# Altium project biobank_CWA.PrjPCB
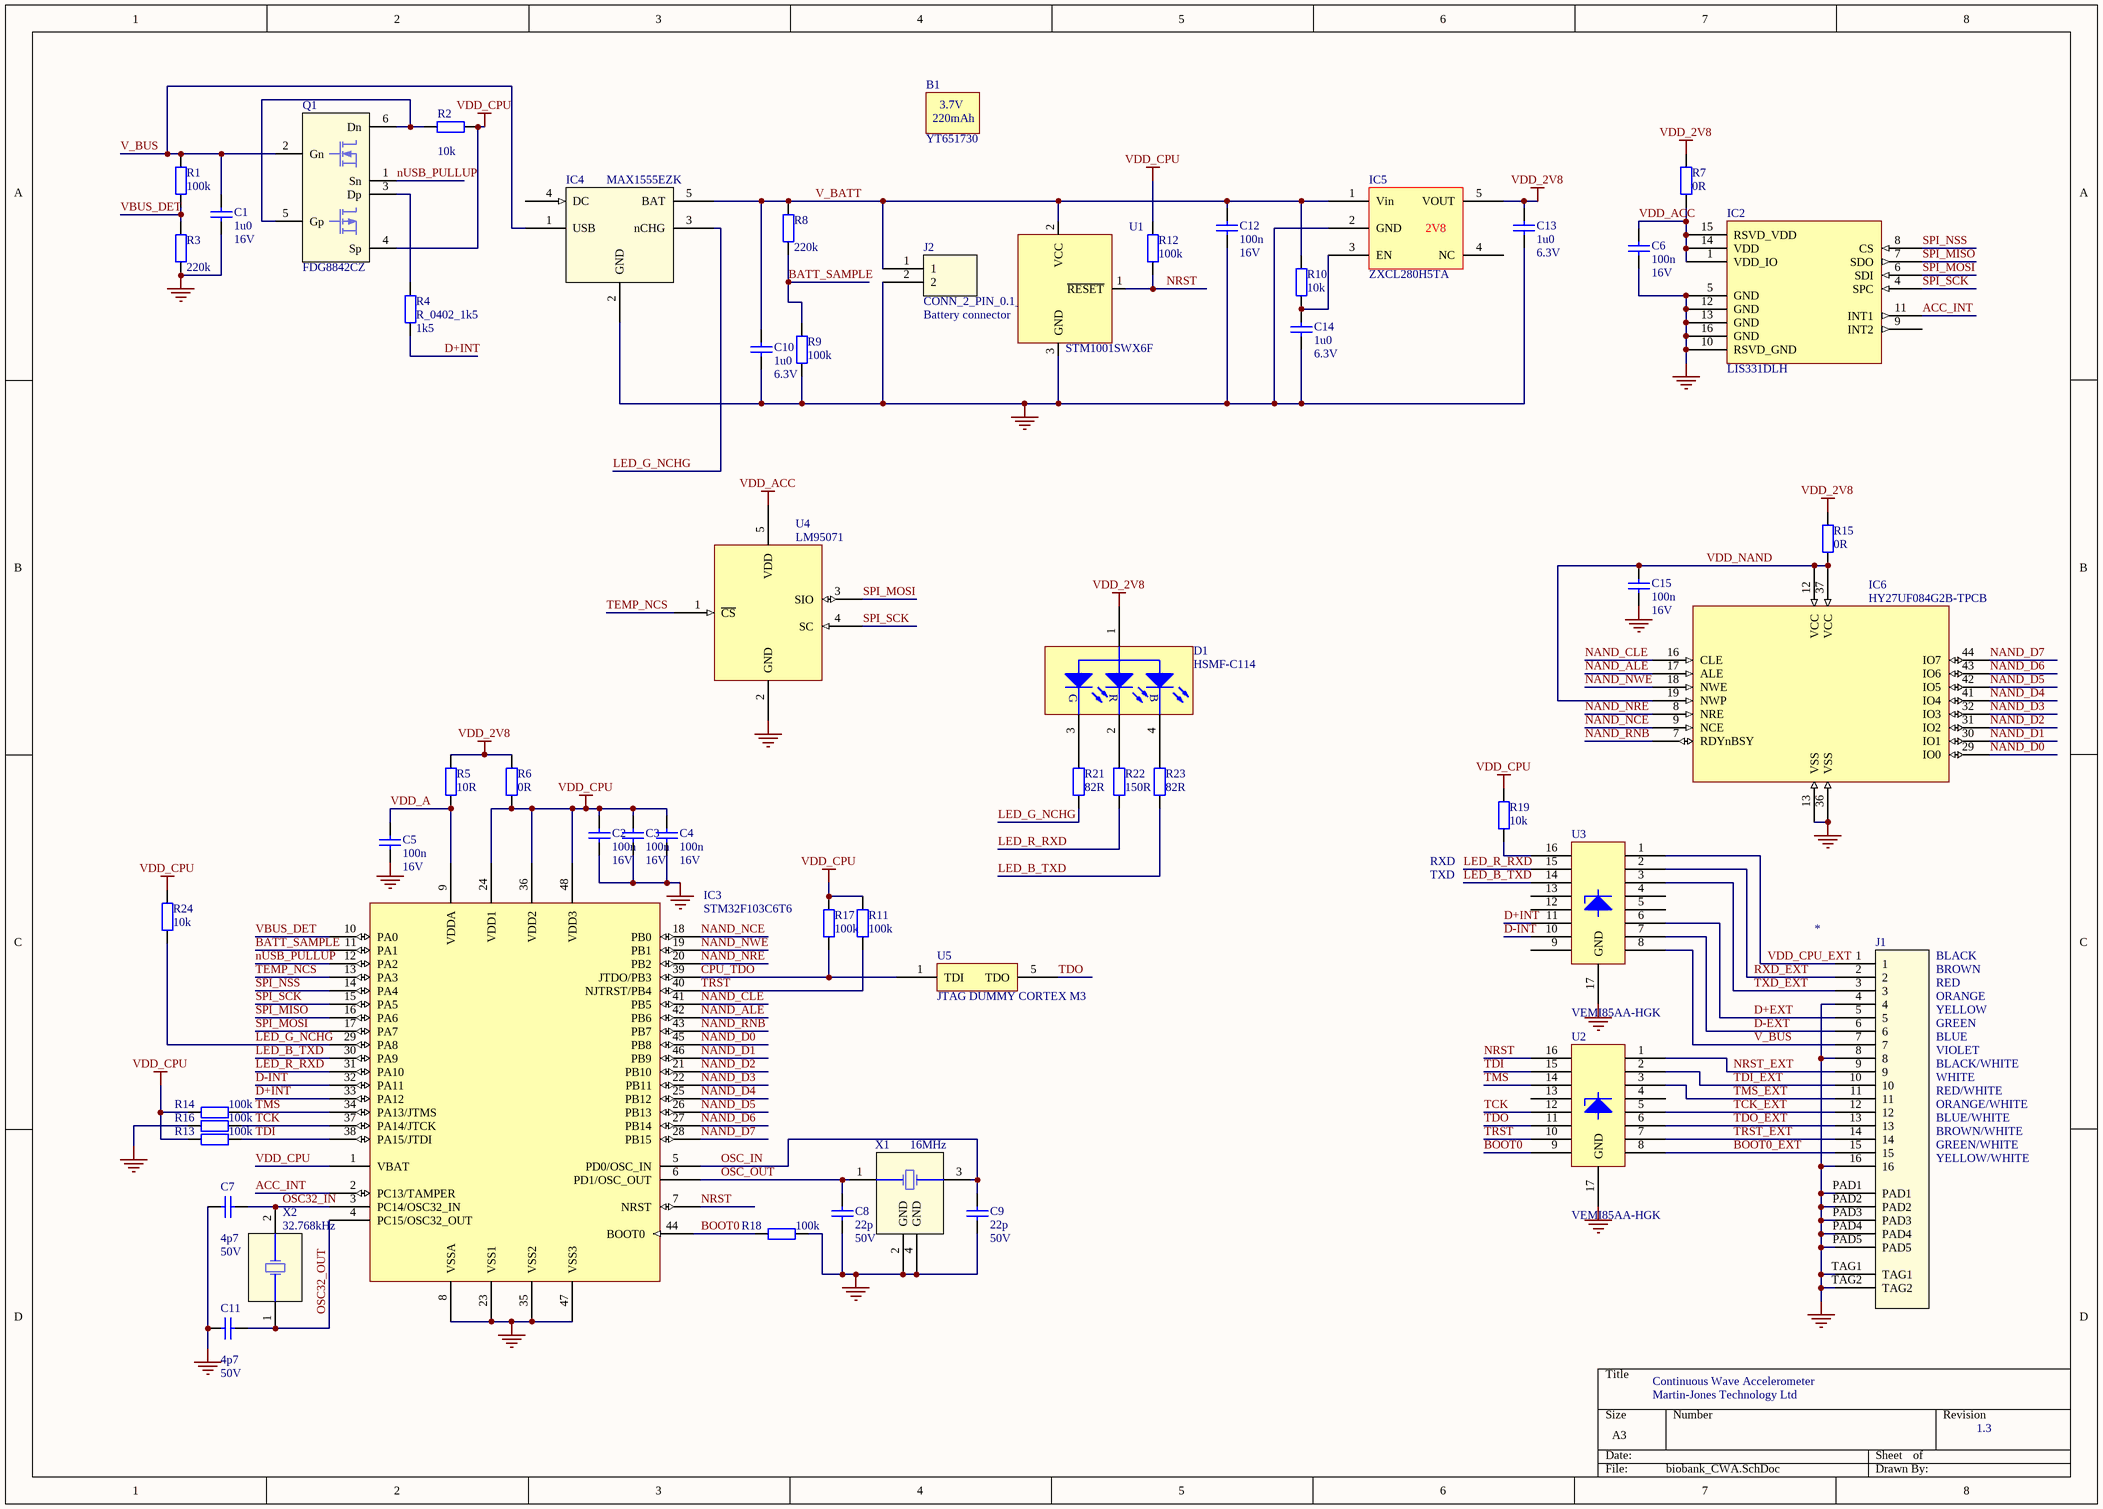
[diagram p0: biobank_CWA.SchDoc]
1 sheet, 55 parts. Net scope: global (net labels, ports and power ports of the same name join across sheets).
Board file: biobank_CWA.PcbDoc

## Sheet biobank_CWA.SchDoc
size A3; PageSetup: Record=PageOptions|CenterHorizontal=True|CenterVertical=True|PrintScale=0.73|XCorrection=1.00|YCorrection=1.00|PrintKind=0|BorderSize=5000000|LeftOffset=0|BottomOffset=0|Orientation=2|PaperLength=1000|PaperWidth=1000|Scale=100|PaperSource=15|PrintQuality=300|MediaType=1|DitherType=10|PaperKind=A4|PrintScaleMode=1

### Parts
B1  YT651730
C1  value 1u0  V: 16V  [0603-NP]  (hidden comment: C_0603_1u0_16V_X7R)
C2  value 100n  V: 16V  [0402-NP]
C3  value 100n  V: 16V  [0402-NP]
C4  value 100n  V: 16V  [0402-NP]
C5  value 100n  V: 16V  [0402-NP]
C6  value 100n  V: 16V  [0402-NP]
C7  value 4p7  V: 50V  [0402-NP]  (hidden comment: C_0402_4p7)
C8  value 22p  V: 50V  [0402-NP]  (hidden comment: C_0402_22p_NPO)
C9  value 22p  V: 50V  [0402-NP]  (hidden comment: C_0402_22p_NPO)
C10  value 1u0  V: 6.3V  [0402-NP]  (hidden comment: C_0402_1u0_6V3_X5R)
C11  value 4p7  V: 50V  [0402-NP]  (hidden comment: C_0402_4p7)
C12  value 100n  V: 16V  [0402-NP]
C13  value 1u0  V: 6.3V  [0402-NP]  (hidden comment: C_0402_1u0_6V3_X5R)
C14  value 1u0  V: 6.3V  [0402-NP]  (hidden comment: C_0402_1u0_6V3_X5R)
C15  value 100n  V: 16V  [0402-NP]
D1  HSMF-C114  [AVAGO_HSMF_C114]
IC2  LIS331DLH  [LGA16]
IC3  STM32F103C6T6  [F-QFP7x7-G48/N]
IC4  MAX1555EZK  [SOT23-5]
IC5  ZXCL280H5TA  [SC70]
IC6  HY27UF084G2B-TPCB  [IC_TSOPI_48_0.5MM]
J1  *  [HANDYLINK_16_WITH_PEGS]
J2  CONN_2_PIN_0.1_NOOUTLINE  [2WAY_0.1_NOOUTLINE]
Q1  FDG8842CZ  [SC70-6]
R1  value 100k  [0402-NP]
R2  value 10k  [0402-NP]  (hidden comment: R_0402_10k)
R3  value 220k  [0402-NP]  (hidden comment: R_0402_220k)
R4  R_0402_1k5  value 1k5  [0402-NP]
R5  value 10R  [0402-NP]  (hidden comment: R_0402_10R)
R6  value 0R  [0402-NP]  (hidden comment: R_0402_0R)
R7  value 0R  [0402-NP]  (hidden comment: R_0402_0R)
R8  value 220k  [0402-NP]  (hidden comment: R_0402_220k)
R9  value 100k  [0402-NP]
R10  value 10k  [0402-NP]  (hidden comment: R_0402_10k)
R11  value 100k  [0402-NP]
R12  value 100k  [0402-NP]
R13  value 100k  [0402-NP]
R14  value 100k  [0402-NP]
R15  value 0R  [0402-NP]  (hidden comment: R_0402_0R)
R16  value 100k  [0402-NP]
R17  value 100k  [0402-NP]
R18  value 100k  [0402-NP]
R19  value 10k  [0402-NP]  (hidden comment: R_0402_10k)
R21  value 82R  [0402-NP]  (hidden comment: R_0402_82R)
R22  value 150R  [0402-NP]
R23  value 82R  [0402-NP]  (hidden comment: R_0402_82R)
R24  value 10k  [0402-NP]  (hidden comment: R_0402_10k)
U1  STM1001SWX6F  [SOT23-3]
U2  VEMI85AA-HGK  [LLP3313-17L]
U3  VEMI85AA-HGK  [LLP3313-17L]
U4  LM95071  [SOT23-5]
U5  JTAG DUMMY CORTEX M3  [0402-NP]
X1  16MHz  [XTAL_25_32]
X2  32.768kHz  [XTAL_15_32]

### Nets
GND: C1.1 C2.1 C3.1 C4.1 C5.1 C6.1 C7.1 C8.1 C9.1 C10.1 C11.1 C12.1 C13.1 C14.1 C15.1 IC2.5(GND) IC2.10(RSVD_GND) IC2.12(GND) IC2.13(GND) IC2.16(GND) IC3.8(VSSA) IC3.23(VSS1) IC3.35(VSS2) IC3.47(VSS3) IC4.2(GND) IC5.2(GND) IC6.13(VSS) IC6.36(VSS) J1.4 J1.8 J1.16 J1.PAD1 J1.PAD2 J1.PAD3 J1.PAD4 J1.PAD5 J1.TAG1 J1.TAG2 J2.2 R3.1 R9.1 R16.1 R18.2 U1.3(GND) U2.17(GND) U3.17(GND) U4.2(GND) X1.2(GND) X1.4(GND)
VDD_2V8: C13.2 D1.1(A) IC5.5(VOUT) R5.2 R6.2 R7.2 R15.1
VDD_ACC: C6.2 IC2.1(VDD_IO) IC2.14(VDD) IC2.15(RSVD_VDD) R7.1 U4.5(VDD)
VDD_CPU: C2.2 C3.2 C4.2 IC3.1(VBAT) IC3.24(VDD1) IC3.36(VDD2) IC3.48(VDD3) Q1.4(Sp) R2.2 R6.1 R11.2 R12.2 R13.1 R14.1 R17.2 R19.2 R24.2
ACC_INT: IC2.11(INT1) IC3.2(PC13/TAMPER)
BATT_SAMPLE: IC3.11(PA1) R8.1 R9.2
BOOT0: IC3.44(BOOT0) R18.1 U2.9
BOOT0_EXT: J1.15 U2.8
CPU_TDO: IC3.39(JTDO/PB3) R17.1 U5.1(TDI)
D+EXT: J1.5 U3.6
D+INT: IC3.33(PA12) R4.1 U3.11
D-EXT: J1.6 U3.7
D-INT: IC3.32(PA11) U3.10
LED_B_TXD: IC3.30(PA9) R23.2 U3.14
LED_G_NCHG: IC3.29(PA8) IC4.3(nCHG) R21.1 R24.1
LED_R_RXD: IC3.31(PA10) R22.1 U3.15
NAND_ALE: IC3.42(PB6) IC6.17(ALE)
NAND_CLE: IC3.41(PB5) IC6.16(CLE)
NAND_D0: IC3.45(PB8) IC6.29(IO0)
NAND_D1: IC3.46(PB9) IC6.30(IO1)
NAND_D2: IC3.21(PB10) IC6.31(IO2)
NAND_D3: IC3.22(PB11) IC6.32(IO3)
NAND_D4: IC3.25(PB12) IC6.41(IO4)
NAND_D5: IC3.26(PB13) IC6.42(IO5)
NAND_D6: IC3.27(PB14) IC6.43(IO6)
NAND_D7: IC3.28(PB15) IC6.44(IO7)
NAND_NCE: IC3.18(PB0) IC6.9(NCE)
NAND_NRE: IC3.20(PB2) IC6.8(NRE)
NAND_NWE: IC3.19(PB1) IC6.18(NWE)
NAND_RNB: IC3.43(PB7) IC6.7(RDYnBSY)
NRST: IC3.7(NRST) R12.1 U1.1(~{RESET}) U2.16
NRST_EXT: J1.9 U2.1
nUSB_PULLUP: IC3.12(PA2) Q1.1(Sn)
OSC32_IN: C7.2 IC3.3(PC14/OSC32_IN) X2.2(OSC2)
OSC32_OUT: C11.2 IC3.4(PC15/OSC32_OUT) X2.1(OSC1)
OSC_IN: C9.2 IC3.5(PD0/OSC_IN) X1.3(OSC2)
OSC_OUT: C8.2 IC3.6(PD1/OSC_OUT) X1.1(OSC1)
RXD_EXT: J1.2 U3.2
SPI_MISO: IC2.7(SDO) IC3.16(PA6)
SPI_MOSI: IC2.6(SDI) IC3.17(PA7) U4.3(SIO)
SPI_NSS: IC2.8(CS) IC3.14(PA4)
SPI_SCK: IC2.4(SPC) IC3.15(PA5) U4.4(SC)
TCK: IC3.37(PA14/JTCK) R16.2 U2.12
TCK_EXT: J1.12 U2.5
TDI: IC3.38(PA15/JTDI) R13.2 U2.15
TDI_EXT: J1.10 U2.2
TDO: U2.11 U5.5(TDO)
TDO_EXT: J1.13 U2.6
TEMP_NCS: IC3.13(PA3) U4.1(~{CS})
TMS: IC3.34(PA13/JTMS) R14.2 U2.14
TMS_EXT: J1.11 U2.3
TRST: IC3.40(NJTRST/PB4) R11.1 U2.10
TRST_EXT: J1.14 U2.7
TXD_EXT: J1.3 U3.3
V_BATT: C10.2 C12.2 IC4.5(BAT) IC5.1(Vin) J2.1 R8.2 R10.1 U1.2(VCC)
V_BUS: C1.2 IC4.1(USB) J1.7 Q1.2(Gn) R1.2 U3.8
VBUS_DET: IC3.10(PA0) R1.1 R3.2
VDD_A: C5.2 IC3.9(VDDA) R5.1
VDD_CPU_EXT: J1.1 U3.1
VDD_NAND: C15.2 IC6.12(VCC) IC6.19(NWP) IC6.37(VCC) R15.2
NetC14_2: C14.2 IC5.3(EN) R10.2
NetD1_2: D1.2(KR) R22.2
NetD1_3: D1.3(KG) R21.2
NetD1_4: D1.4(KB) R23.1
NetQ1_3: Q1.3(Dp) R4.2
NetQ1_5: Q1.5(Gp) Q1.6(Dn) R2.1
NetR19_1: R19.1 U3.16

Not connected (* = marked no-connect by the designer): IC2 9(INT2); IC4 4(DC); IC5 4(NC); IC6 1(NC) 2(NC) 3(NC) 4(NC) 5(NC) 10(NC) 11(NC) 14(NC) 15(NC) 20(NC) 21(NC) 22(NC) 23(NC) 24(NC) 34(NC) 35(NC) 39(NC); U2 4 13; U3 4 5 9 12 13

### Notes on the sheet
- Battery connector
- RXD
- TXD
- BLACK
- BROWN
- RED
- ORANGE
- YELLOW
- GREEN
- BLUE
- VIOLET
- BLACK/WHITE
- WHITE
- RED/WHITE
- ORANGE/WHITE
- BLUE/WHITE
- BROWN/WHITE
- GREEN/WHITE
- YELLOW/WHITE
- Continuous Wave Accelerometer
- Martin-Jones Technology Ltd
- 1.3

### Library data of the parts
B1 = BATTERY_YUNTONG_YT651730: Yuntong YT651730 3.7V 220mAh LiPoly battery; Manufacturer part number: YT651730 with PCB, wire ended
C1 = C_0603_1u0_16V_X7R: Capacitor
C2-C6 C12 C15 = C_0402_100n_X7R: Capacitor
C7 C11 = C_0402_4p7: Capacitor
C8 C9 = C_0402_22p_NPO: Capacitor
C10 C13 C14 = C_0402_1u0_6V3_X5R: Capacitor
D1 = HSMF-C114: Avago HSMF-C114 RGB LED
IC2 = LIS331DLH: ST digital accelerometer
IC3 = STM32F103C6T6: Manufacturer: ST
IC4 = MAX1555EZK: LiIon USB battery charger; Manufacturer: Maxim Integrated Products
IC5 = ZXCL280H5TA: SC70 LDO 2.8V Regulator; Manufacturer: Diodes Inc
IC6 = HY27UF084G2B-TPCB: Hynix 4Gbit NAND Flash
J1 = CONN_HANDYLINK_16_0.8_MOLEX_WITH_PEGS: Molex Handylink 16 way 0.8mm; Manufacturer Part Number: 44828-1162
J2 = CONN_2_PIN_0.1_NOOUTLINE: 2 pin 0.1in header
Q1 = FDG8842CZ: Manufacturer: Fairchild
R1 R9 R11-R14 R16-R18 = R_0402_100k: Resistor
R2 R10 R19 R24 = R_0402_10k: Resistor
R3 R8 = R_0402_220k: Resistor
R4 = R_0402_1k5: Resistor
R5 = R_0402_10R: Resistor
R6 R7 R15 = R_0402_0R: Resistor
R21 R23 = R_0402_82R: Resistor
R22 = R_0402_150R: Resistor
U1 = STM1001SWX6F: Reset supervisor 2.93V open drain; Manufacturer: ST
U2 U3 = VEMI85AA-HGK: 8-way ESD protection; Manufacturer: Vishay
U4 = LM95071: Temperature sensor; Manufacturer: National Semiconductor; Manufacturer Part Number: LM95071CIMF
U5 = JTAG_DUMMY_CORTEX_M3: Dummy device so XJTAG is happy with number of devices in chain; pin to pad: 5>2; Manufacturer: Generic; Manufacturer Part Number: 0R resistor 0402
X1 = XTAL_C3E_16MHz: 16MHz crystal 2.5x3,2mm; Manufacturer: Aker; Manufacturer Part Number: C3E-16.000-12-3030-X
X2 = XTAL_15_32_32.768kHz_9pF: 32.768kHz 1.5x3.2mm 9pF load; Manufacturer: Micro Crystal; Manufacturer Part Number: CC7V-T1A 32.768KHZ +-20PPM 9PF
